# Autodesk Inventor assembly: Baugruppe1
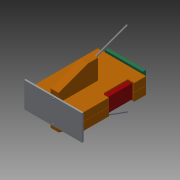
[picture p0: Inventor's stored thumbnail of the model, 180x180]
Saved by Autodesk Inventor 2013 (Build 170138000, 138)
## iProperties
Created: 2012-11
Part Number: Baugruppe1
Document SubType Name: Assembly
Designer: otto
Author: otto
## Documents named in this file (8)
- C:\Users\otto\Documents\Studium Dell\5. Semester\K-Lehre\CAD\Baugruppe1.iam
- C:\Users\otto\Documents\Studium Dell\5. Semester\K-Lehre\CAD\Bauteil1 (2).ipt
- C:\Users\otto\Documents\Studium Dell\5. Semester\K-Lehre\CAD\kern.ipt
- C:\Users\otto\Documents\Studium Dell\5. Semester\K-Lehre\CAD\abstreifer.ipt
- C:\Users\otto\Documents\Studium Dell\5. Semester\K-Lehre\CAD\backe rechts_MIR.ipt
- C:\Users\otto\Documents\Studium Dell\5. Semester\K-Lehre\CAD\Aufspannplatte.ipt
- C:\Users\otto\Documents\Studium Dell\5. Semester\K-Lehre\CAD\EN 10060 - 10 - 500.ipt
- C:\Users\otto\Documents\Studium Dell\5. Semester\K-Lehre\CAD\backe rechts_MIR_MIR.ipt
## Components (8 placed, 7 different names)
1. Stehsammler — Passend:1, Passend:2, Passend:8, Passend:14, Fluchtend:2, Passend:17, Passend:18
2. kern:1 — Passend:1, Passend:2, Passend:17, Passend:20, Passend:21
3. abstreifer:1 — Passend:20, Passend:21, Passend:22
4. Aufspannplatte:1 — Passend:11, Passend:12, Fluchtend:1, Fluchtend:2, Passend:15, Fluchtend:3
5. EN 10060 - 10 - 500:1 — Passend:12, Passend:19
6. EN 10060 - 10 - 500:2 — Passend:11, Passend:24
7. backe links — Fluchtend:3, Fluchtend:4, Passend:24
8. backe rechts — Passend:8, Fluchtend:1, Passend:14, Passend:15, Passend:18, Passend:19, Passend:22, Fluchtend:4
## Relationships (18: Mate 14, Flush 4)
- Passend:1 [Mate]: Stehsammler ↔ kern:1
- Passend:2 [Mate]: Stehsammler ↔ kern:1
- Passend:8 [Mate]: Stehsammler ↔ backe rechts
- Passend:11 [Mate]: Aufspannplatte:1 ↔ EN 10060 - 10 - 500:2
- Passend:12 [Mate]: Aufspannplatte:1 ↔ EN 10060 - 10 - 500:1
- Fluchtend:1 [Flush]: Aufspannplatte:1 ↔ backe rechts
- Passend:14 [Mate]: Stehsammler ↔ backe rechts
- Fluchtend:2 [Flush]: Stehsammler ↔ Aufspannplatte:1
- Passend:15 [Mate]: Aufspannplatte:1 ↔ backe rechts
- Passend:17 [Mate]: Stehsammler ↔ kern:1
- Passend:18 [Mate]: Stehsammler ↔ backe rechts
- Passend:19 [Mate]: EN 10060 - 10 - 500:1 ↔ backe rechts
- Passend:20 [Mate]: kern:1 ↔ abstreifer:1
- Passend:21 [Mate]: kern:1 ↔ abstreifer:1
- Passend:22 [Mate]: abstreifer:1 ↔ backe rechts
- Fluchtend:3 [Flush]: Aufspannplatte:1 ↔ backe links
- Fluchtend:4 [Flush]: backe links ↔ backe rechts
- Passend:24 [Mate]: EN 10060 - 10 - 500:2 ↔ backe links
